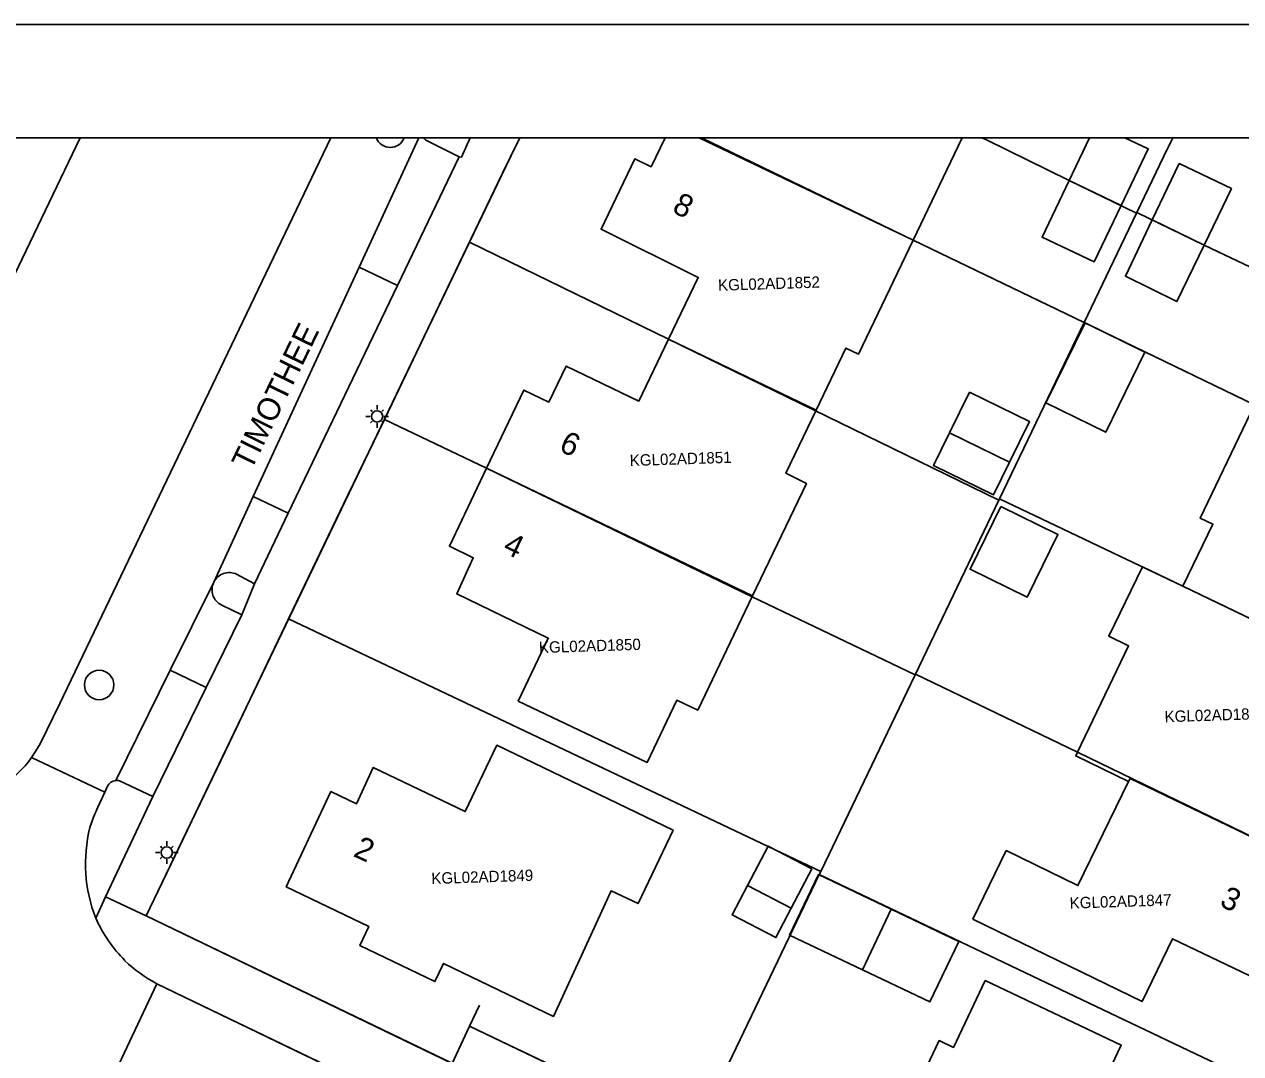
# Model space of a CAD drawing. Extents: x 124901 to 125496, y 515369 to 515789.
# Drawn here: x 125375.1 to 125428.8, y 515743.6 to 515789 of the extents above; entities that cross this region are included whole.
import ezdxf

# ---------------------------------------------------------------- set-up
doc = ezdxf.new("R2010")
doc.units = 0
for name, color, linetype in [('Alg Kaders', 7, 'Continuous'), ('Gebouw', 7, 'Continuous'), ('Inrit', 7, 'Continuous'), ('Lichtmast', 7, 'Continuous'), ('Luifel', 7, 'Continuous'), ('Onbegroeid terrein', 7, 'Continuous'), ('Overige bouwwerk', 7, 'Continuous'), ('Parkeren', 7, 'Continuous'), ('Perceelnummers', 7, 'Continuous'), ('Perceelsgrenzen', 7, 'Continuous'), ('Putten', 7, 'Continuous'), ('Scheiding', 7, 'Continuous'), ('Teksten', 7, 'Continuous'), ('Vegetatie', 7, 'Continuous'), ('Voetpad', 7, 'Continuous'), ('Wegen drempel verkeerseiland', 7, 'Continuous'), ('Wegen lokale weg', 7, 'Continuous')]:
    doc.layers.add(name, color=color, linetype=linetype)

msp = doc.modelspace()

# ---------------------------------------------------------------- linework, layer by layer
at = {"layer": 'Alg Kaders'}
for points in [[(125495.925, 515789.043), (124901.425, 515789.043), (124901.425, 515368.543), (125495.925, 515368.543)], [(125490.925, 515784.043), (124906.425, 515784.043), (124906.425, 515373.543), (125490.925, 515373.543)]]:
    msp.add_lwpolyline(points, close=True, dxfattribs=at)
at = {"layer": 'Gebouw'}
for points in [[(125403.405, 515784.043), (125402.789, 515782.759), (125402.071, 515783.104), (125400.584, 515780.008), (125404.868, 515777.881), (125403.561, 515775.152), (125410.077, 515772.026), (125411.391, 515774.764), (125411.945, 515774.498), (125414.358, 515779.525), (125404.911, 515784.043)], [(125404.911, 515784.043), (125414.358, 515779.525), (125416.526, 515784.043)], [(125422.145, 515784.043), (125421.241, 515782.151), (125423.537, 515781.052), (125424.733, 515783.545), (125423.695, 515784.043)]]:
    msp.add_lwpolyline(points, dxfattribs=at)
for points in [[(125427.2, 515779.304), (125428.401, 515781.797), (125426.101, 515782.899), (125424.911, 515780.414)], [(125422.34, 515778.559), (125423.537, 515781.052), (125421.241, 515782.151), (125420.048, 515779.654)], [(125425.998, 515776.81), (125427.2, 515779.304), (125424.911, 515780.414), (125423.72, 515777.929)], [(125395.531, 515769.464), (125407.27, 515763.835), (125409.647, 515768.793), (125408.74, 515769.238), (125410.077, 515772.026), (125403.561, 515775.152), (125402.255, 515772.422), (125399.037, 515773.962), (125398.273, 515772.382), (125397.17, 515772.906)], [(125439.9, 515764.91), (125439.184, 515765.246), (125440.023, 515766.994), (125440.075, 515767.102), (125431.668, 515771.141), (125431.77, 515771.355), (125429.508, 515772.425), (125429.412, 515772.225), (125427.025, 515767.257), (125427.582, 515766.99), (125426.263, 515764.254), (125431.944, 515761.517), (125433.254, 515764.255), (125438.397, 515761.799)], [(125418.608, 515769.726), (125415.967, 515771.019), (125415.261, 515769.576), (125417.901, 515768.283)], [(125404.848, 515758.784), (125407.27, 515763.835), (125395.531, 515769.464), (125393.891, 515766.022), (125394.945, 515765.51), (125394.211, 515763.917), (125398.251, 515761.971), (125396.93, 515759.19), (125402.621, 515756.487), (125403.923, 515759.227)], [(125434.674, 515756.78), (125430.634, 515758.779), (125431.944, 515761.517), (125426.263, 515764.254), (125424.47, 515765.108), (125422.989, 515762.047), (125423.865, 515761.623), (125421.595, 515756.902), (125421.531, 515756.769), (125423.866, 515755.644), (125423.931, 515755.778), (125433.351, 515751.249), (125435, 515754.672), (125433.913, 515755.191)], [(125402.213, 515750.257), (125403.762, 515753.5), (125395.989, 515757.243), (125394.59, 515754.314), (125390.525, 515756.257), (125389.792, 515754.662), (125388.664, 515755.194), (125386.689, 515750.996), (125390.331, 515749.244), (125389.937, 515748.401), (125393.252, 515746.814), (125393.634, 515747.613), (125398.483, 515745.28), (125401.027, 515750.824)], [(125416.994, 515749.573), (125424.461, 515745.935), (125425.798, 515748.707), (125429.858, 515746.762), (125430.62, 515748.357), (125431.702, 515747.826), (125433.351, 515751.249), (125423.931, 515755.778), (125423.866, 515755.644), (125421.629, 515751.05), (125418.464, 515752.591)], [(125407.956, 515752.792), (125407.051, 515751.057), (125408.975, 515750.054), (125409.88, 515751.789)], [(125412.115, 515747.338), (125415.093, 515745.919), (125416.365, 515748.587), (125413.387, 515750.006)], [(125423.536, 515744.006), (125417.541, 515746.861), (125416.135, 515743.909), (125415.497, 515744.211), (125412.913, 515738.759), (125412.822, 515738.808), (125412.676, 515738.535), (125417.528, 515736.209), (125417.109, 515735.335), (125420.434, 515733.734), (125420.834, 515734.572), (125424.504, 515732.82), (125426.486, 515736.981), (125425.411, 515737.485), (125426.183, 515739.085), (125422.121, 515741.035)]]:
    msp.add_lwpolyline(points, close=True, dxfattribs=at)
at = {"layer": 'Inrit'}
msp.add_line((125392.536, 515784.043), (125389.902, 515778.334), dxfattribs=at)
for points in [[(125389.902, 515778.334), (125391.595, 515777.524), (125394.318, 515783.2), (125392.941, 515783.883)], [(125386.775, 515767.479), (125385.234, 515768.218), (125383.488, 515764.432)], [(125384.499, 515764.783), (125385.281, 515764.366), (125386.775, 515767.479)], [(125383.488, 515764.432), (125381.568, 515760.552)], [(125381.568, 515760.552), (125383.16, 515759.788), (125384.731, 515762.988), (125383.842, 515763.422)]]:
    msp.add_lwpolyline(points, dxfattribs=at)
for centre, radius, start, end in [((125393.117, 515784.276), 0.431, 212.739, 245.8494), ((125384.168, 515764.104), 0.755, 64.0176, 154.2744), ((125384.168, 515764.103), 0.755, 154.183, 244.4477)]:
    msp.add_arc(centre, radius, start, end, dxfattribs=at)
at = {"layer": 'Lichtmast'}
for p, q in [((125390.485, 515771.961), (125390.415, 515772.032)), ((125390.697, 515772.049), (125390.697, 515772.249)), ((125390.909, 515771.961), (125390.98, 515772.033)), ((125390.397, 515771.75), (125390.197, 515771.749)), ((125390.485, 515771.537), (125390.413, 515771.466)), ((125390.697, 515771.449), (125390.697, 515771.249)), ((125390.909, 515771.537), (125390.979, 515771.466)), ((125390.997, 515771.749), (125391.197, 515771.749)), ((125381.416, 515752.809), (125381.416, 515753.009)), ((125381.116, 515752.51), (125380.916, 515752.509)), ((125381.204, 515752.721), (125381.134, 515752.792)), ((125381.628, 515752.721), (125381.699, 515752.793)), ((125381.716, 515752.509), (125381.916, 515752.509)), ((125381.204, 515752.297), (125381.132, 515752.226)), ((125381.416, 515752.209), (125381.416, 515752.009)), ((125381.628, 515752.297), (125381.698, 515752.226))]:
    msp.add_line(p, q, dxfattribs=at)
for centre in [(125390.697, 515771.749), (125381.416, 515752.509)]:
    msp.add_circle(centre, 0.25, dxfattribs=at)
at = {"layer": 'Luifel'}
for points in [[(125416.847, 515772.815), (125415.967, 515771.019), (125418.608, 515769.726), (125419.487, 515771.521)], [(125408.904, 515748.87), (125412.115, 515747.338), (125413.387, 515750.006), (125410.176, 515751.537)], [(125407.051, 515751.057), (125406.374, 515749.759), (125408.298, 515748.756), (125408.975, 515750.054)]]:
    msp.add_lwpolyline(points, close=True, dxfattribs=at)
at = {"layer": 'Onbegroeid terrein'}
for points in [[(125396.992, 515784.043), (125396.24, 515782.475), (125389.82, 515769.117), (125383.87, 515756.723), (125380.503, 515749.71), (125427.387, 515727.139), (125451.745, 515778.087), (125454.621, 515784.043)], [(125416.526, 515784.043), (125414.358, 515779.525), (125411.945, 515774.498), (125411.391, 515774.764), (125410.077, 515772.026), (125408.74, 515769.238), (125409.647, 515768.793), (125407.27, 515763.835), (125404.848, 515758.784), (125403.923, 515759.227), (125402.621, 515756.487), (125396.93, 515759.19), (125398.251, 515761.971), (125394.211, 515763.917), (125394.945, 515765.51), (125393.891, 515766.022), (125395.531, 515769.464), (125397.17, 515772.906), (125398.273, 515772.382), (125399.037, 515773.962), (125402.255, 515772.422), (125403.561, 515775.152), (125404.868, 515777.881), (125400.584, 515780.008), (125402.071, 515783.104), (125402.789, 515782.759), (125403.405, 515784.043)], [(125423.695, 515784.043), (125424.733, 515783.545), (125423.537, 515781.052), (125422.34, 515778.559), (125420.048, 515779.654), (125421.241, 515782.151), (125422.145, 515784.043)], [(125429.858, 515746.762), (125425.798, 515748.707), (125424.461, 515745.935), (125416.994, 515749.573), (125418.464, 515752.591), (125421.629, 515751.05), (125423.866, 515755.644), (125421.531, 515756.769), (125421.595, 515756.902), (125423.865, 515761.623), (125422.989, 515762.047), (125424.47, 515765.108), (125426.263, 515764.254), (125427.582, 515766.99), (125427.025, 515767.257), (125429.412, 515772.225)]]:
    msp.add_lwpolyline(points, dxfattribs=at)
for points in [[(125428.401, 515781.797), (125427.2, 515779.304), (125425.998, 515776.81), (125423.72, 515777.929), (125424.911, 515780.414), (125426.101, 515782.899)], [(125415.967, 515771.019), (125418.608, 515769.726), (125417.901, 515768.283), (125415.261, 515769.576)], [(125395.989, 515757.243), (125403.762, 515753.5), (125402.213, 515750.257), (125401.027, 515750.824), (125398.483, 515745.28), (125393.634, 515747.613), (125393.252, 515746.814), (125389.937, 515748.401), (125390.331, 515749.244), (125386.689, 515750.996), (125388.664, 515755.194), (125389.792, 515754.662), (125390.525, 515756.257), (125394.59, 515754.314)], [(125407.051, 515751.057), (125407.956, 515752.792), (125409.88, 515751.789), (125408.975, 515750.054)], [(125413.387, 515750.006), (125416.365, 515748.587), (125415.093, 515745.919), (125412.115, 515747.338)], [(125417.541, 515746.861), (125423.536, 515744.006), (125422.121, 515741.035), (125426.183, 515739.085), (125425.411, 515737.485), (125426.486, 515736.981), (125424.504, 515732.82), (125420.834, 515734.572), (125420.434, 515733.734), (125417.109, 515735.335), (125417.528, 515736.209), (125412.676, 515738.535), (125412.822, 515738.808), (125412.913, 515738.759), (125415.497, 515744.211), (125416.135, 515743.909)]]:
    msp.add_lwpolyline(points, close=True, dxfattribs=at)
at = {"layer": 'Overige bouwwerk'}
for points in [[(125421.945, 515775.87), (125420.218, 515772.343), (125422.859, 515771.05), (125424.586, 515774.577)], [(125418.227, 515767.775), (125416.87, 515765.003), (125419.383, 515763.773), (125420.741, 515766.545)]]:
    msp.add_lwpolyline(points, close=True, dxfattribs=at)
at = {"layer": 'Parkeren'}
msp.add_lwpolyline([(125385.234, 515768.218), (125386.775, 515767.479), (125391.595, 515777.524), (125389.902, 515778.334)], close=True, dxfattribs=at)
for points in [[(125383.16, 515759.788), (125381.568, 515760.552), (125379.162, 515755.686)], [(125379.33, 515755.672), (125380.797, 515754.975), (125383.16, 515759.788)]]:
    msp.add_lwpolyline(points, dxfattribs=at)
msp.add_arc((125379.209, 515755.23), 0.459, 74.6437, 95.829, dxfattribs=at)
at = {"layer": 'Perceelsgrenzen'}
for points in [[(125431.007, 515734.711), (125427.387, 515727.139), (125413.755, 515733.701), (125414.614, 515735.357), (125404.72, 515740.089), (125394.782, 515744.843), (125394.008, 515743.208), (125380.503, 515749.71), (125384.163, 515757.333), (125386.795, 515762.816), (125389.428, 515768.301), (125391.02, 515771.613), (125392.618, 515774.939), (125394.78, 515779.439), (125396.748, 515783.534), (125396.992, 515784.043)], [(125405.017, 515784.043), (125414.353, 515779.515), (125421.905, 515775.893), (125418.169, 515768.109), (125418.144, 515768.057), (125394.78, 515779.439), (125396.748, 515783.534), (125396.992, 515784.043)], [(125417.388, 515784.043), (125417.588, 515783.947), (125421.236, 515782.151), (125424.219, 515780.719), (125423.042, 515778.262), (125421.905, 515775.893), (125414.353, 515779.515), (125405.017, 515784.043)], [(125425.812, 515784.043), (125425.42, 515783.225), (125424.231, 515780.744), (125424.219, 515780.719), (125421.236, 515782.151), (125417.588, 515783.947), (125417.388, 515784.043)], [(125429.866, 515784.043), (125436.361, 515780.929), (125445.494, 515776.552), (125449.979, 515774.394), (125447.653, 515769.528), (125443.16, 515771.683), (125434.027, 515776.061), (125433.125, 515776.493), (125428.096, 515778.871), (125427.199, 515779.303), (125424.231, 515780.744), (125425.42, 515783.225), (125425.812, 515784.043)]]:
    msp.add_lwpolyline(points, dxfattribs=at)
for points in [[(125445.325, 515764.648), (125440.822, 515766.82), (125429.426, 515772.254), (125421.905, 515775.893), (125423.042, 515778.262), (125424.219, 515780.719), (125424.231, 515780.744), (125427.199, 515779.303), (125428.096, 515778.871), (125433.125, 515776.493), (125434.027, 515776.061), (125443.16, 515771.683), (125447.653, 515769.528), (125447.624, 515769.467)], [(125391.02, 515771.613), (125392.618, 515774.939), (125394.78, 515779.439), (125418.144, 515768.057), (125414.461, 515760.383), (125414.442, 515760.344), (125407.25, 515763.793), (125395.533, 515769.469)], [(125441.604, 515756.876), (125426.263, 515764.254), (125418.169, 515768.109), (125421.905, 515775.893), (125429.426, 515772.254), (125440.822, 515766.82), (125445.325, 515764.648), (125445.273, 515764.539), (125442.991, 515759.777)], [(125391.02, 515771.613), (125395.533, 515769.469), (125407.25, 515763.793), (125414.442, 515760.344), (125410.278, 515751.668), (125386.795, 515762.816), (125389.428, 515768.301)], [(125437.872, 515749.069), (125433.351, 515751.249), (125421.613, 515756.939), (125414.461, 515760.383), (125418.144, 515768.057), (125418.169, 515768.109), (125426.263, 515764.254), (125441.604, 515756.876), (125439.52, 515752.517)], [(125404.72, 515740.089), (125394.782, 515744.843), (125394.008, 515743.208), (125380.503, 515749.71), (125384.163, 515757.333), (125386.795, 515762.816), (125410.278, 515751.668), (125410.215, 515751.536)], [(125433.703, 515740.35), (125410.215, 515751.536), (125410.278, 515751.668), (125414.442, 515760.344), (125414.461, 515760.383), (125421.613, 515756.939), (125433.351, 515751.249), (125437.872, 515749.069), (125435.948, 515745.045)], [(125404.72, 515740.089), (125410.215, 515751.536), (125433.703, 515740.35), (125431.007, 515734.711), (125427.387, 515727.139), (125413.755, 515733.701), (125414.614, 515735.357)]]:
    msp.add_lwpolyline(points, close=True, dxfattribs=at)
at = {"layer": 'Putten'}
msp.add_circle((125378.43, 515759.9), 0.65, dxfattribs=at)
msp.add_arc((125391.28, 515784.26), 0.65, 199.5024, 340.4976, dxfattribs=at)
at = {"layer": 'Scheiding'}
for points in [[(125395.225, 515745.779), (125394.782, 515744.843)], [(125415.054, 515736.205), (125414.614, 515735.357), (125394.782, 515744.843)]]:
    msp.add_lwpolyline(points, dxfattribs=at)
at = {"layer": 'Vegetatie'}
for points in [[(125377.598, 515784.043), (125367.35, 515762.716), (125366.907, 515761.798)], [(125375.45, 515756.695), (125375.644, 515756.994), (125375.826, 515757.299), (125376.693, 515759.089), (125388.661, 515784.043)], [(125392.941, 515783.883), (125394.318, 515783.2), (125394.425, 515783.184), (125394.809, 515784.043)], [(125384.731, 515762.988), (125385.281, 515764.366), (125384.499, 515764.783)], [(125383.842, 515763.422), (125384.731, 515762.988)], [(125378.795, 515755.432), (125378.678, 515755.178), (125378.369, 515754.509), (125378.179, 515754.065), (125378.025, 515753.606)], [(125378.28, 515749.612), (125378.719, 515750.547), (125380.797, 515754.975), (125379.33, 515755.672)]]:
    msp.add_lwpolyline(points, dxfattribs=at)
for centre, radius, start, end in [((125393.117, 515784.276), 0.431, 212.739, 245.8494), ((125384.168, 515764.104), 0.755, 64.0176, 154.2744), ((125384.168, 515764.103), 0.755, 154.183, 244.4477), ((125371.371, 515759.667), 5.047, 303.1002, 323.9235), ((125379.209, 515755.226), 0.462, 95.8075, 153.5666), ((125379.209, 515755.23), 0.459, 74.6437, 95.829), ((125384.463, 515752.012), 6.632, 166.0921, 201.2141)]:
    msp.add_arc(centre, radius, start, end, dxfattribs=at)
at = {"layer": 'Voetpad'}
msp.add_line((125380.977, 515746.721), (125427.246, 515724.451), dxfattribs=at)
for points in [[(125454.621, 515784.043), (125451.745, 515778.087), (125427.387, 515727.139), (125380.503, 515749.71), (125378.719, 515750.547), (125378.28, 515749.612)], [(125394.809, 515784.043), (125394.425, 515783.184), (125394.318, 515783.2), (125391.595, 515777.524), (125386.775, 515767.479), (125385.281, 515764.366), (125384.731, 515762.988), (125383.16, 515759.788), (125380.797, 515754.975), (125378.719, 515750.547), (125380.503, 515749.71), (125383.87, 515756.723), (125389.82, 515769.117), (125396.24, 515782.475), (125396.992, 515784.043)]]:
    msp.add_lwpolyline(points, dxfattribs=at)
for centre, radius, start, end in [((125384.276, 515752.361), 6.596, 204.6291, 224.4969), ((125383.945, 515752.304), 6.323, 226.2338, 242.0076)]:
    msp.add_arc(centre, radius, start, end, dxfattribs=at)
at = {"layer": 'Wegen drempel verkeerseiland'}
for points in [[(125378.025, 515753.606), (125378.179, 515754.065), (125378.369, 515754.509), (125378.678, 515755.178), (125375.45, 515756.695)], [(125378.821, 515742.134), (125380.977, 515746.721)]]:
    msp.add_lwpolyline(points, dxfattribs=at)
for centre, radius, start, end in [((125371.371, 515759.667), 5.047, 303.1002, 323.9235), ((125384.463, 515752.012), 6.632, 166.0921, 201.2141), ((125384.276, 515752.361), 6.596, 204.6291, 224.4969), ((125383.945, 515752.304), 6.323, 226.2338, 242.0076)]:
    msp.add_arc(centre, radius, start, end, dxfattribs=at)
at = {"layer": 'Wegen lokale weg'}
for points in [[(125366.907, 515761.798), (125367.35, 515762.716), (125377.598, 515784.043)], [(125388.661, 515784.043), (125376.693, 515759.089), (125375.826, 515757.299), (125375.644, 515756.994), (125375.45, 515756.695), (125378.678, 515755.178), (125378.795, 515755.432)], [(125379.162, 515755.686), (125381.568, 515760.552), (125383.488, 515764.432), (125385.234, 515768.218), (125389.902, 515778.334), (125392.536, 515784.043)], [(125427.246, 515724.451), (125380.977, 515746.721), (125378.821, 515742.134), (125428.125, 515718.465)]]:
    msp.add_lwpolyline(points, dxfattribs=at)
msp.add_arc((125379.209, 515755.226), 0.462, 95.8075, 153.5666, dxfattribs=at)

# ---------------------------------------------------------------- texts
at = {"layer": 'Perceelnummers'}
for s, rotation, p in [('KGL02AD1852', 1.8328, (125405.752, 515777.285)), ('KGL02AD1851', 1.8328, (125401.854, 515769.556)), ('KGL02AD1850', 1.8327, (125397.848, 515761.305)), ('KGL02AD1846', 1.833, (125425.457, 515758.254)), ('KGL02AD1849', 1.8326, (125393.1, 515751.117)), ('KGL02AD1847', 1.833, (125421.269, 515750.031))]:
    msp.add_text(s, height=0.5, rotation=rotation, dxfattribs=at).set_placement(p)
at = {"layer": 'Teksten'}
for s, rotation, p in [('8', 333.6, (125403.672, 515780.779)), ('TIMOTHEE', 64, (125385.138, 515769.317)), ('6', 334.4, (125398.676, 515770.252)), ('4', 334.4, (125396.196, 515765.772)), ('2', 335.3, (125389.602, 515752.364)), ('3', 334, (125427.833, 515750.177))]:
    msp.add_text(s, height=1, rotation=rotation, dxfattribs=at).set_placement(p)

doc.saveas('drawing.dxf')
